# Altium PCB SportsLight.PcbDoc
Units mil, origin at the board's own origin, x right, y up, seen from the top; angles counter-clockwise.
Board outline 1968.64 x 1181.1 mil, 4 copper layers (Top Layer, GND02, PWR03, Bottom Layer), stack 23.756 mil thick; 45 components, 29 nets, 173 pads, 54 vias.
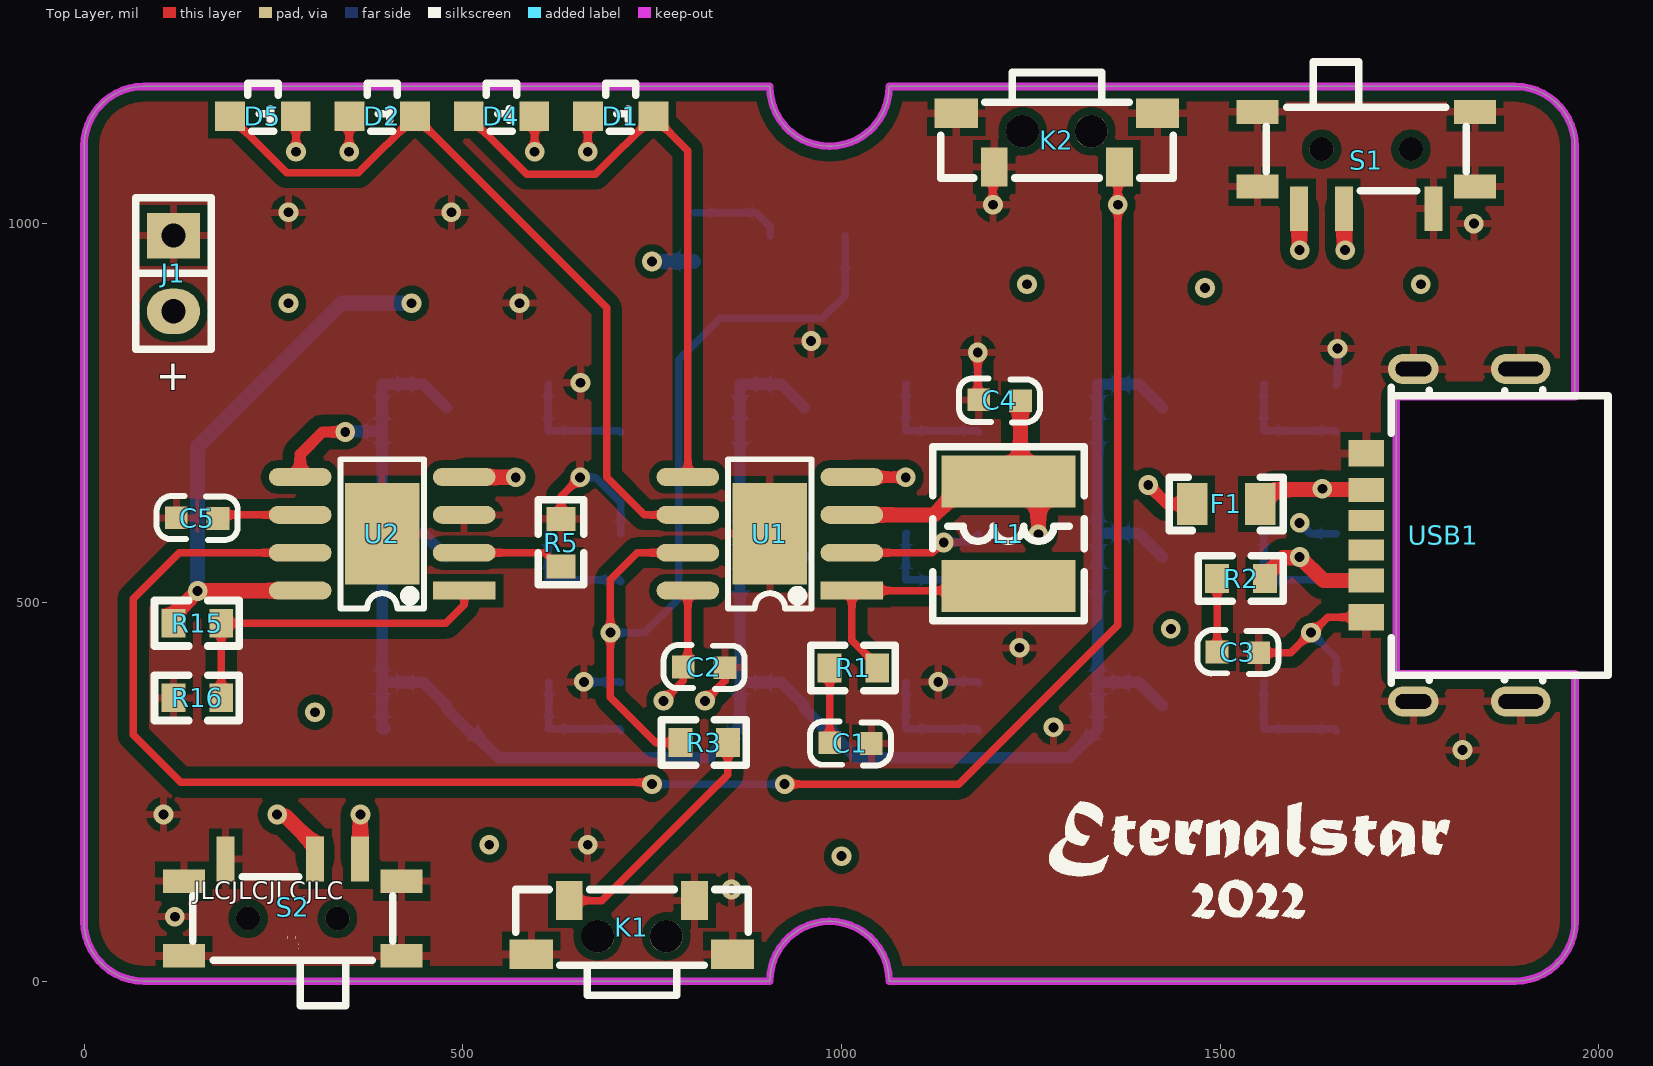
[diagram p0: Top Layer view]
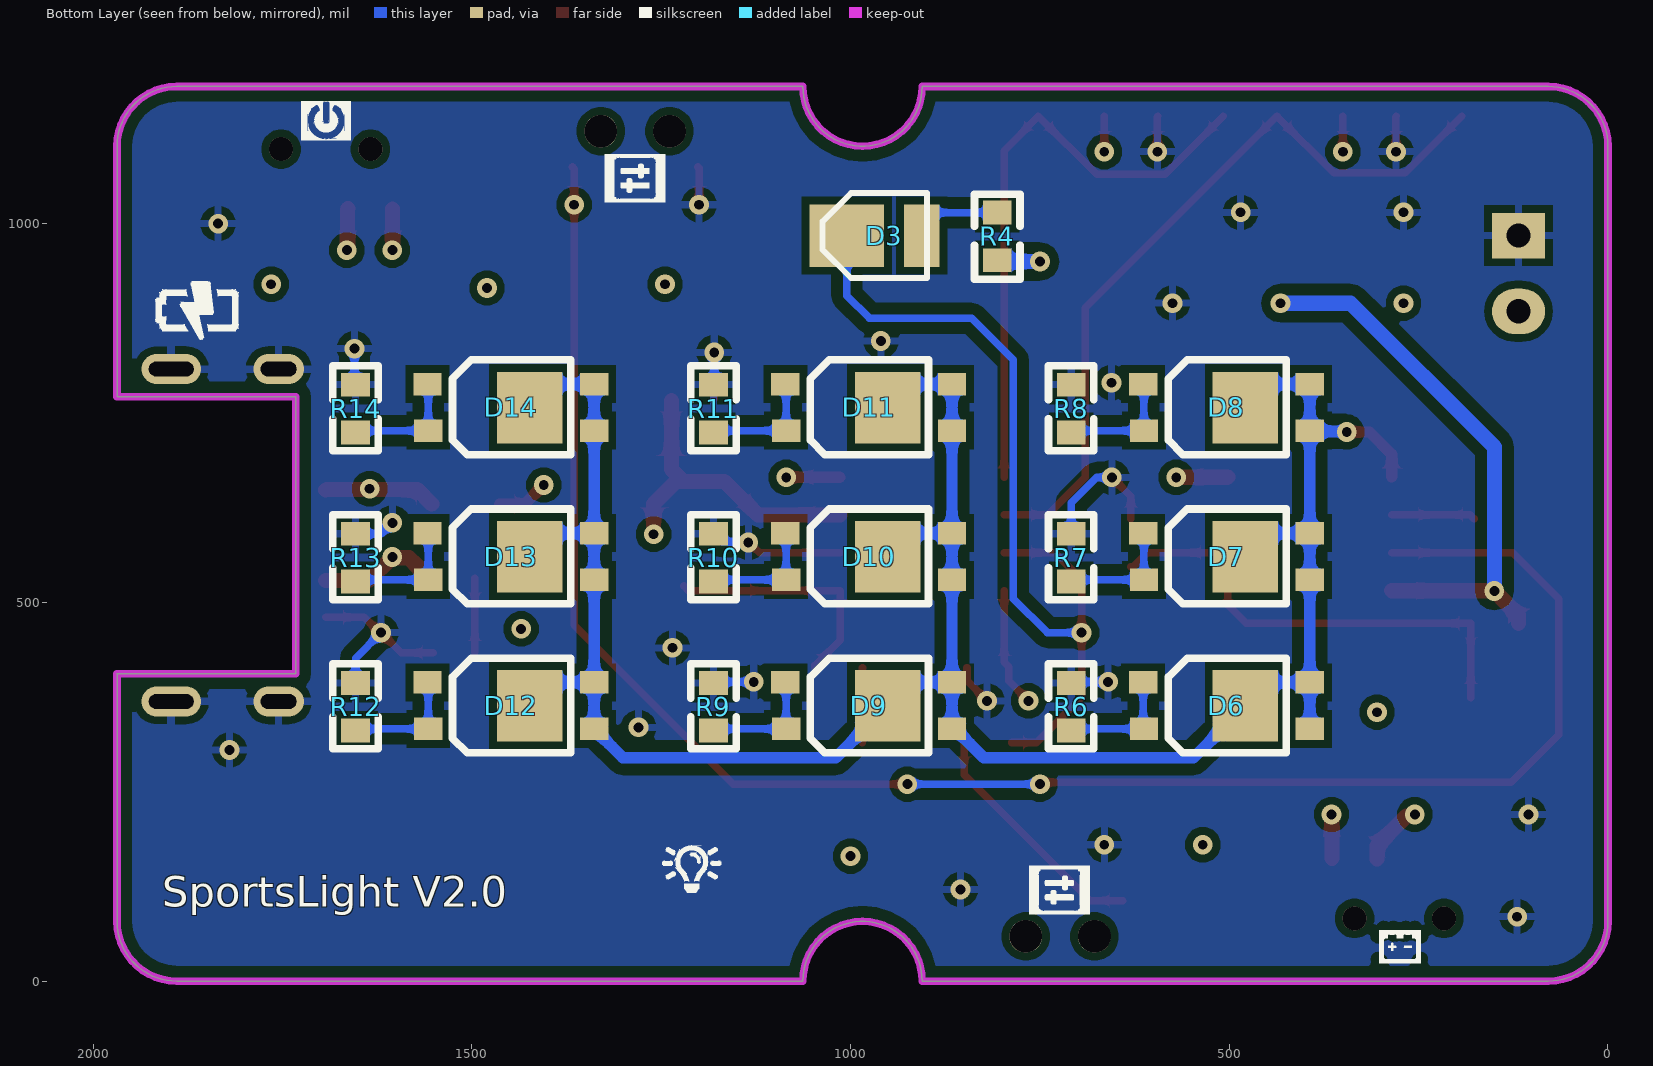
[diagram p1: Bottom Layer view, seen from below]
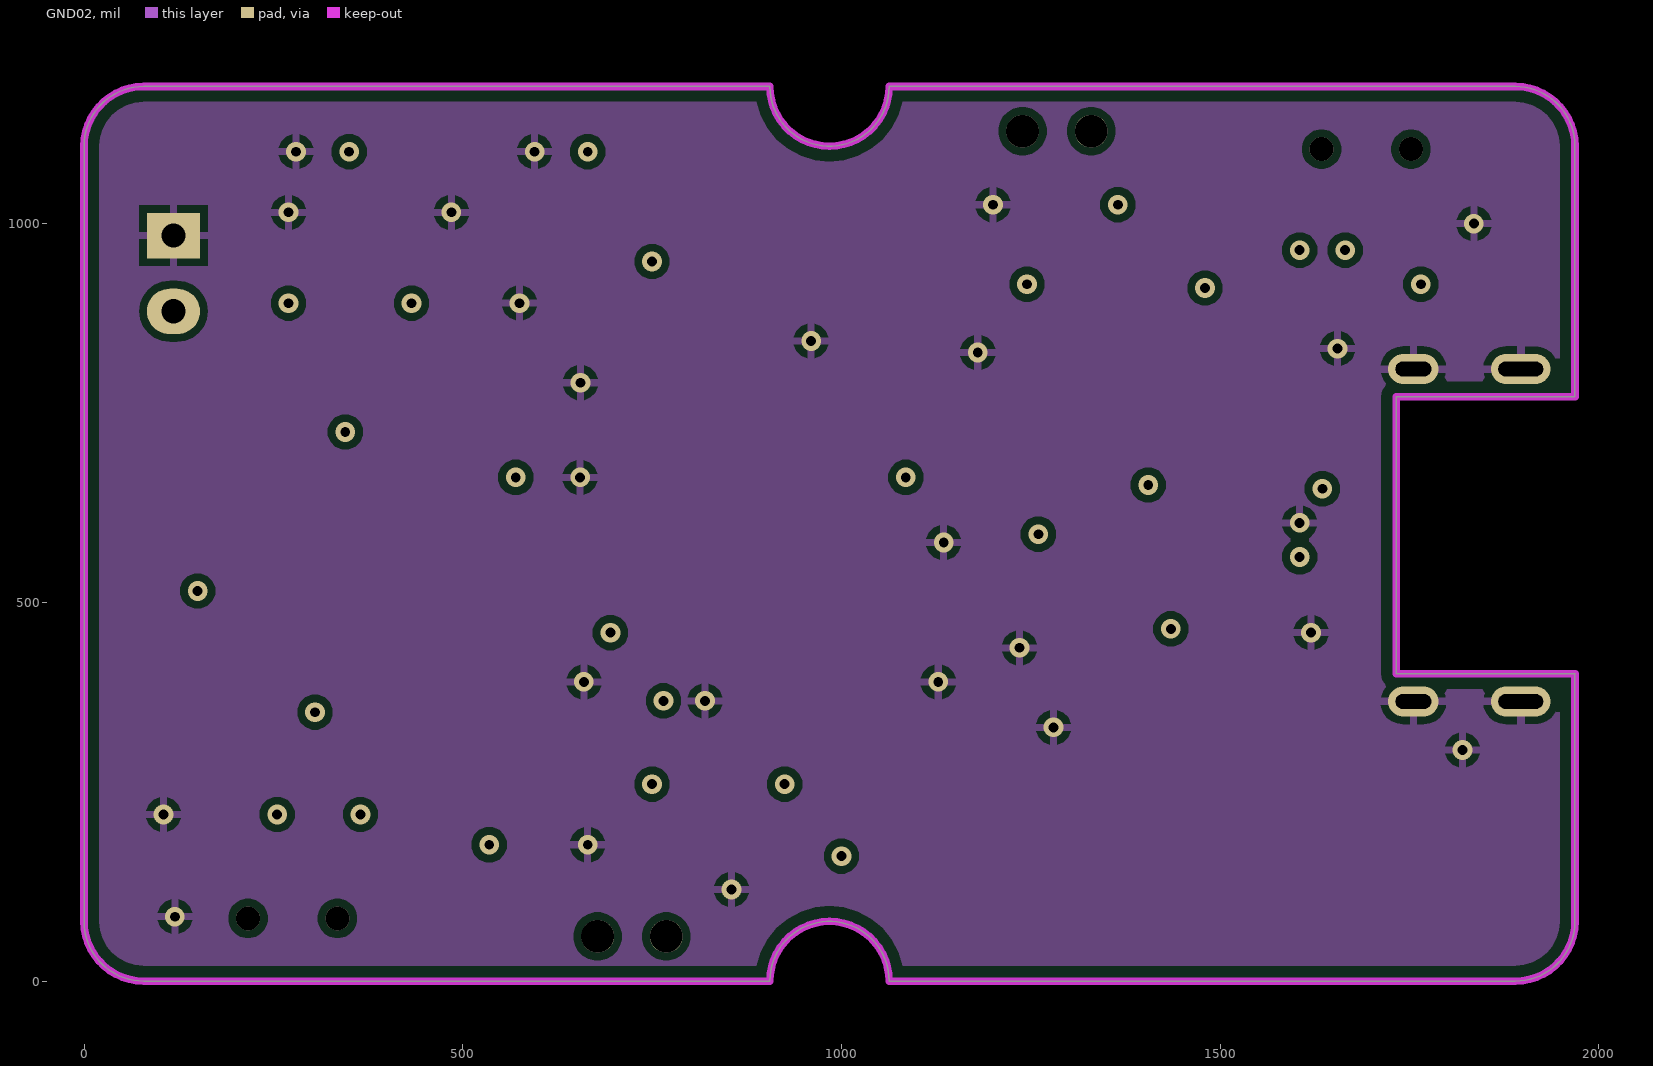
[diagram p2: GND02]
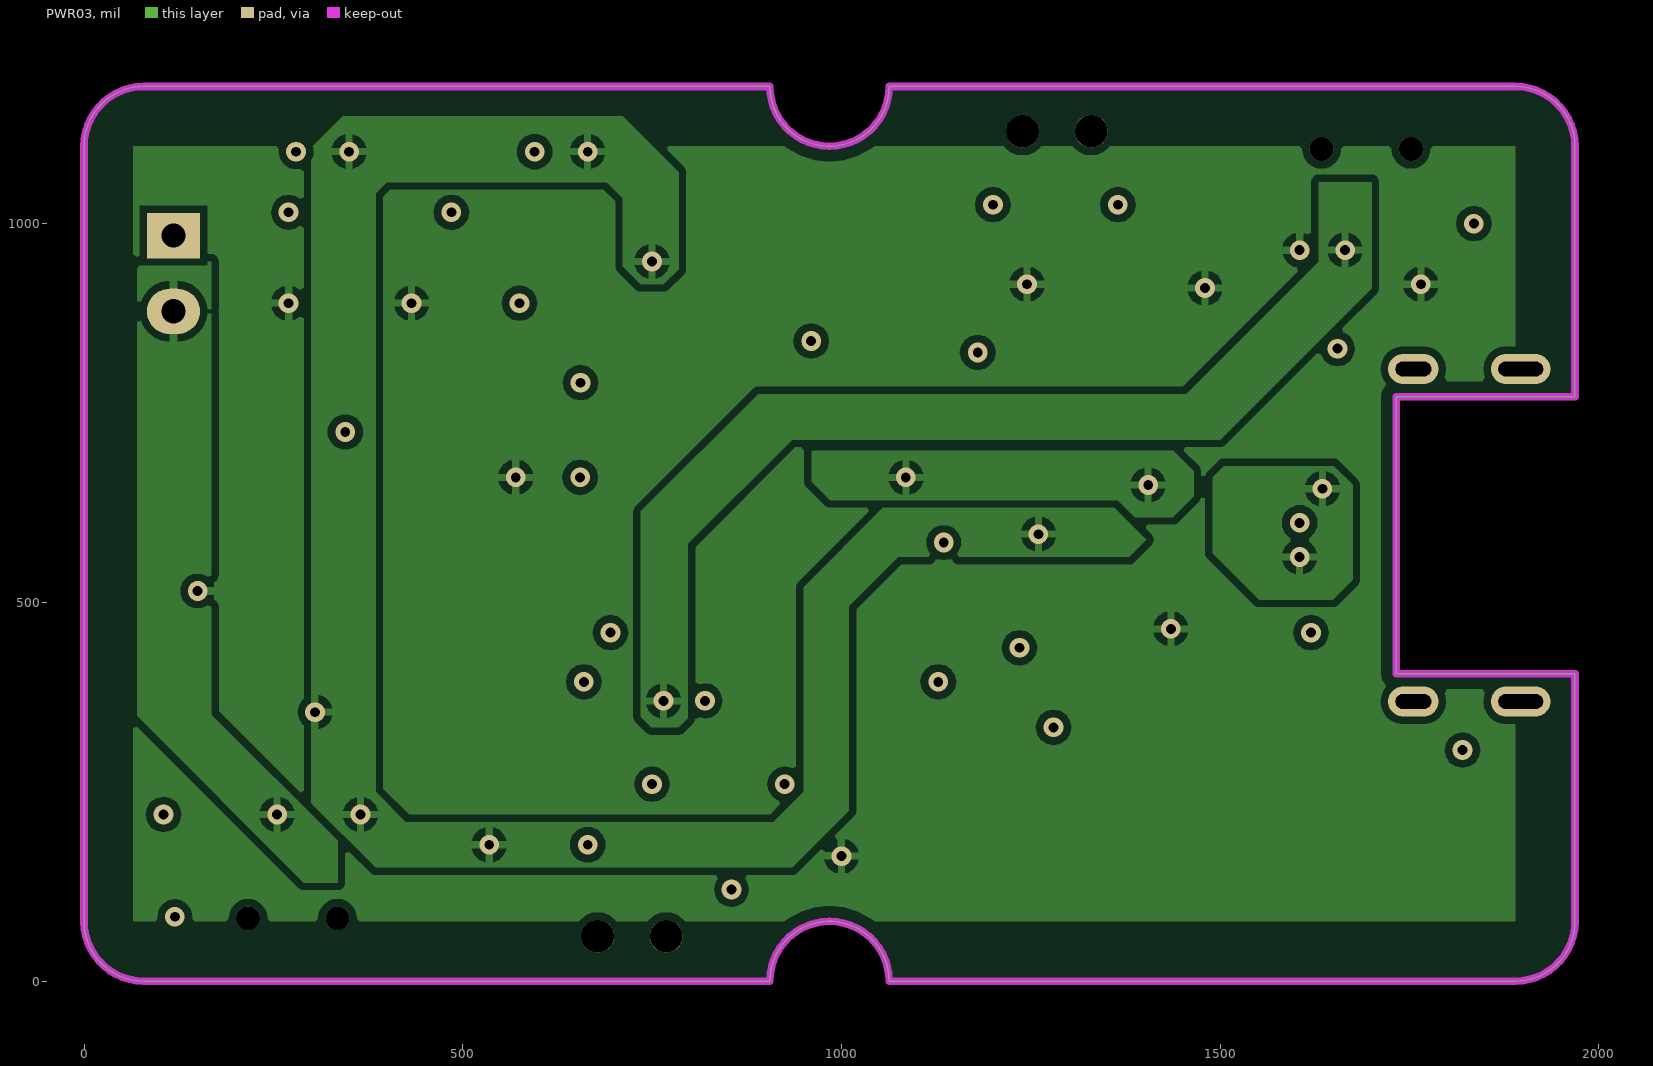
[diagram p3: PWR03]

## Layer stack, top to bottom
Top Solder: solder mask 0.4, Solder Resist, Dk 3.5
Top Layer: signal copper 1.4
Dielectric 1: dielectric 12.6, FR-4, Dk 4.8
GND02: signal copper 1.378
Dielectric 2: prepreg 2.8, PP-006, Dk 4.1
PWR03: signal copper 1.378
Dielectric 3: prepreg 2.8, PP-006, Dk 4.1
Bottom Layer: signal copper 1.4
Bottom Solder: solder mask 0.4, Solder Resist, Dk 3.5

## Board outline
78.74,0 905.51,0 cw(c984.25,0) 1062.99,0 1889.76,0 ccw(c1889.76,78.74) 1968.5,78.74 1968.5,405.38 1968.64,405.51 1732.28,405.51 1732.28,771.65 1968.5,771.65 1968.5,1102.49 1968.5,1102.36 ccw(c1889.76,1102.36) 1889.76,1181.1 1062.99,1181.1 cw(c984.25,1181.1) 905.51,1181.1 78.74,1181.1 ccw(c78.74,1102.36) 0,1102.36 0,78.74 ccw(c78.74,78.74)
cut-out: -1025,-915 -1015,-915 -1015,-905 -1025,-905
cut-out: -1025,-915 -1015,-915 -1015,-905 -1025,-905
cut-out: -1025,-915 -1015,-915 -1015,-905 -1025,-905

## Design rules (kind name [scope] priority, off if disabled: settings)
Clearance [All] p1: gap=10 ignorepadtopadclearanceinfootprint=TRUE except(15: Arc-Fill Arc-Poly Arc-Region Track-Fill Track-Poly Track-Region)
DiffPairsRouting [All] p1: maxlimit=10 minlimit=3.5 mostfreqgap=10 toplayer_minwidth=3.5 toplayer_maxwidth=15 toplayer_prefwidth=15 midlayer1_minwidth=3.5 midlayer1_maxwidth=15 midlayer1_prefwidth=15 midlayer2_minwidth=3.5 midlayer2_maxwidth=15 midlayer2_prefwidth=15 bottomlayer_minwidth=3.5 bottomlayer_maxwidth=15 bottomlayer_prefwidth=15 maxuncoupledlength=500
HoleSize [All] p1: absolutevalues=TRUE maxlimit=248.03 minlimit=7.87 maxpercent=80.000 minpercent=20.000
MinimumSolderMaskSliver [All] p1: minsoldermaskwidth=0
NetAntennae [InNet('No Net')] p1: netantennaetolerance=0
PolygonConnect [All] p1: connectstyle=Relief reliefconductorwidth=10 reliefentries=4 polygonreliefangle="90 Angle" airgapwidth=10
RoutingVias [All] p1: holewidth=28 width=50 viastyle="Through Hole" minholewidth=7.87 minwidth=15.75 maxholewidth=248.03 maxwidth=255.91
SilkToSolderMaskClearance [IsPad] p1: minsilkscreentomaskgap=0 clearancetoexposedcopper=TRUE
SolderMaskExpansion [All] p1: expansion=4 istentingtop=FALSE
Width [All] p1: maxlimit=30 minlimit=5 preferedwidth=10
25 further rules are at their usual default settings.

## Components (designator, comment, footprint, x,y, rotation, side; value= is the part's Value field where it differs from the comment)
C1 "3.3nF" 0603C 984.25,314.96 r0 top locked
C2 "10uF" 0603C 846.46,413.39 r180 top locked
C3 "1uF" 0603C 1551.13,433.07 r180 top locked
C4 "10uF" 0603C 1181.1,767.72 r0 top
C5 "MODE" 0603C 177.17,610.24 r180 top locked
D1 "LED4" LED-0602-RD 708.66,1141.73 r0 top locked
D2 "LED2" LED-0602-RD 393.7,1141.73 r0 top locked
D3 "LED-3528" LED-3528R 905.51,984.25 r0 bottom
D4 "LED3" LED-0602-RD 551.18,1141.73 r0 top locked
D5 "LED1" LED-0602-RD 236.22,1141.73 r0 top locked
D6 "LED-5630" LED-5630W 393.7,393.7 r180 bottom locked
D7 "LED-5630" LED-5630W 393.7,590.55 r180 bottom locked
D8 "LED-5630" LED-5630W 393.7,787.4 r180 bottom locked
D9 "LED-5630" LED-5630W 866.14,393.7 r180 bottom locked
D10 "LED-5630" LED-5630W 866.14,590.55 r180 bottom locked
D11 "LED-5630" LED-5630W 866.14,787.4 r180 bottom locked
D12 "LED-5630" LED-5630W 1338.58,393.7 r180 bottom locked
D13 "LED-5630" LED-5630W 1338.58,590.55 r180 bottom locked
D14 "LED-5630" LED-5630W 1338.58,787.4 r180 bottom
F1 "6V1A" FUSE-0805 1548.06,629.92 r180 top locked
J1 "CE" "Pin HDR1X2/2.54mm-S" 118.11,984.25 r0 top
K1 "KEY" SMD-3.5x7.8x2.5_C 590.55,35.43 r0 top locked
K2 "KEY" SMD-3.5x7.8x2.5_C 1417.32,1145.67 r180 top
L1 "1.5uH" CD43 1220.47,590.55 r270 top
R1 "0.5R" 0603R 984.25,413.39 r0 top locked
R2 "1K" 0603R 1496.06,531.5 r0 top locked
R3 "30K" 0603R 787.4,314.96 r0 top
R4 "33R" 0603R 806.36,951.63 r90 bottom locked
R5 "MODE" 0603R 629.92,610.24 r270 top locked
R6 "MODE" 0603R 708.66,393.7 r270 bottom locked
R7 "MODE" 0603R 708.66,590.55 r270 bottom
R8 "MODE" 0603R 708.66,787.4 r270 bottom locked
R9 "MODE" 0603R 1181.1,393.7 r270 bottom locked
R10 "MODE" 0603R 1181.1,590.55 r270 bottom locked
R11 "MODE" 0603R 1181.1,787.4 r270 bottom locked
R12 "MODE" 0603R 1653.54,393.7 r270 bottom locked
R13 "MODE" 0603R 1653.54,590.55 r270 bottom locked
R14 "MODE" 0603R 1653.54,787.4 r270 bottom locked
R15 "MODE" 0603R 118.11,472.44 r0 top locked
R16 "MODE" 0603R 118.11,374.02 r0 top locked
S1 "MSK-12C01-07" MSK-12C01-07 1692.91,1098.43 r180 top locked
S2 "MSK-12C01-07" MSK-12C01-07 275.59,82.68 r0 top locked
U1 "SY3511" ESOP8 905.51,590.55 r180 top locked
U2 "CN5730" ESOP8 393.7,590.55 r180 top
USB1 "USB-C 6P CB0.8(073)" USB-C-SMD_TYPE-C-6P-CB0.8-073 1692.91,480.32 r90 top locked

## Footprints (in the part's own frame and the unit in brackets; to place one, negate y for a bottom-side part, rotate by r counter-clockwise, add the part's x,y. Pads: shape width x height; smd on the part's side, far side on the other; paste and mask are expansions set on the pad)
0603C [mil]
  rect 30x30 smd: 1(0.21,-0.35) 2(55.21,-1.35)
  silkscreen extent -26,-30 81,28, body extent -1,-15 62,17, height 12
0603R [mm]
  rect 0.8x0.965 smd: 1(0,0) 2(1.6,0)
  silkscreen extent -0.64,-0.76 2.21,0.76, body extent -0.04,-0.41 1.56,0.41, height 0.45
CD43 [mm] "4.5*4*3.2mm（长宽高）"
  rect 1.75x4.5 smd: 1(-1.75,0) 2(1.75,0)
  silkscreen extent -2.92,-2.54 2.92,2.54, body extent -2.13,-1.87 2.29,2.13, height 3.3
ESOP8 [mm]
  rect 2.1x0.6 smd: 1(-2.75,1.905)
  oval 2.1x0.6 smd: 2(-2.75,0.635) 3(-2.75,-0.635) 4(-2.75,-1.905) 5(2.75,-1.905) 6(2.75,-0.635) 7(2.75,0.635) 8(2.75,1.905)
  rect 2.5x3.4 smd paste-2: 9(0,0)
  rect 0.9x0.7 on Top Paste: 10(-0.625,1.1) 10(-0.625,0) 10(-0.625,-1.1) 11(0.65,1.1) 11(0.65,0) 11(0.65,-1.1)
  silkscreen extent -1.4,-2.5 1.4,2.5, body extent -3.05,-2.5 2.95,2.5, height 1.53
FUSE-0805 [mil]
  rect 40x55 smd: 1(-5,0) 2(85,0)
  silkscreen extent -35,-35 115,35, body extent 0,-24 79,24, height 20
LED-0602-RD [mm]
  rect 1x1 smd: 1(-1.1,0) 2(1.1,0)
  silkscreen extent -0.51,-0.51 0.51,1.11
LED-3528R [mm]
  rect 1.2x2.1 smd: A(0.013,0)
  rect 2.5x2.1 smd: K(2.527,0)
  silkscreen extent -0.17,-1.42 3.34,1.42, body extent -0.25,-1.4 3.25,1.4, height 1.95
LED-5630W [mm]
  rect 2.2x2.4 smd: A(-2.159,-0.768)
  rect 0.95x0.75 smd: A(0,-1.543) A(0,0.019) K(-5.588,0.019) K(-5.563,-1.543)
  silkscreen extent -4.75,-2.34 -0.79,0.83, body extent -5.57,-2.29 0.23,0.71, height 0.95
MSK-12C01-07 [mm]
  rect 1.4x0.8 smd: 0(-3.65,-1.25) 0(-3.65,1.25) 0(3.65,-1.25) 0(3.65,1.25)
  rect 0.6x1.5 smd: 1(2.25,1.996) 2(0.75,1.996) 3(-2.25,1.996)
  round 0.8 hole 0.8: " "(-1.5,0) " "(1.5,0)
  silkscreen extent -3.35,-2.92 3.35,1.4, body extent -3.92,-2.89 3.92,2.41, height 1.5
"Pin HDR1X2/2.54mm-S" [mil]
  rect 70x60 hole 32: 1(0,0)
  oval 70x60 hole 32: 2(0,-100)
  silkscreen extent -50,-150 50,50, body extent -50,-150 50,50, height 336
SMD-3.5x7.8x2.5_C [mm]
  rect 1.45x1 smd: 1(0,0) 2(6.75,0)
  rect 0.9x1.3 smd: 3(1.275,1.8) 4(5.475,1.8)
  round 1.1 hole 1.1 unplated: ""(2.225,0.6) ""(4.525,0.6)
  silkscreen extent -0.52,-1.37 7.27,2.17
USB-C-SMD_TYPE-C-6P-CB0.8-073 [mm]
  rect 0.9x1.2 smd: 1(0,0) 6(5.5,0)
  rect 0.8x1.2 smd: 2(1.23,0) 5(4.27,0)
  rect 0.7x1.2 smd: 3(2.25,0) 4(3.25,0)
  oval 1x1.7 hole 0.5 slot 1.2 at 90 deg: 7(-2.825,-1.58) 8(8.325,-1.58)
  oval 1x2 hole 0.5 slot 1.5 at 90 deg: 7(-2.825,-5.18) 8(8.325,-5.18)
  silkscreen extent -2.21,-8.11 7.71,-0.84

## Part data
C1 C2 C3 C4 C5: library part CAP, "无极性电容"
D1 D2 D4 D5: library part LED
F1: library part FUSE
J1: library part "Pin HDR1X2"
L1: library part INDUCTOR, "INDUCTOR"
R1 R2 R3 R4 R5 R6 R7 R8 R9 R10 R11 R12 R13 R14 R15 R16: library part RES
U1: "移动电源单芯片"
U2: "LED集成驱动电路"

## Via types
v1: diameter 26, hole 13, Top Layer to Bottom Layer, 54 vias

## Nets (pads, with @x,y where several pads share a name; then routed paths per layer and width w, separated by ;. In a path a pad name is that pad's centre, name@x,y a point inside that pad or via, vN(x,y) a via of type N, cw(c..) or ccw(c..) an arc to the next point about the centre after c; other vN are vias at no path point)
BAT: C4.2 D1.1 D2.1 L1.1 R4.1 S2.1 U1.3 | length 640
  Top Layer w10: v1(350,1095) 350,1141.34 D2.1 ; v1(665,1095) 665,1141.38 D1.1
  Top Layer w15: S2.1 S2.1@364.59,161.67 ; v1@364.59,219.59 v1(365,220)
  Top Layer w20: S2.1@364.59,161.67 v1@364.59,219.59 ; U1.3 1122.44,615.55 1166.34,659.45 L1.1 ; C4.2 1236.32,675.29 L1.1 ; v1(1260,590) 1260,630 1230.55,659.45 L1.1
  Bottom Layer w10: R4.1@804.73,950 R4.1
  Bottom Layer w20: v1(750,950) R4.1@804.73,950
  other v1: 535,180 305,355
GND: C1.2 C2.1 C3.1 C4.1 C5.2 D4.2 D5.2 J1.1 K1.1 K1.2 K1.4 K2.1 K2.2 K2.4 R5.1 R6.1 R7.1 R8.1 R9.1 R10.1 R11.1 R12.1 R13.1 R14.1 R16.1 S1.0 S1.3 S2.0 S2.3 U1.2 U1.9 U2.3 U2.9 USB1.1 USB1.6 USB1.7 USB1.8 | length 1103.8
  Top Layer w10: D5.2 280,1141.26 v1(280,1095) ; D4.2 595,1141.22 v1(595,1095) ; R5.1 629.92,639.92 v1(655,665) ; v1(820,370) 846.24,396.24 C2.1 ; U1.2 1120.13,565.55 1125.68,571.1 1127,571.1 v1(1135,579.1) ; v1(1180,830) 1180,768.68 C4.1 ; v1(1200,1025) 1200,1073.03 K2.4 ; C3.1 1593.43,433.43 v1(1620,460) 1621.8,460 1642.11,480.32 USB1.1
  Bottom Layer w10: v1(655,665) 675,665 708.66,631.34 R7.1 ; v1(660,395) 707.36,395 R6.1 ; v1(1127.84,395) 1179.8,395 R9.1 ; v1(1135,579.1) 1135.7,579.8 1170.35,579.8 R10.1 ; v1(1180,830) 1180,788.5 R11.1 ; v1(1605,605) 1605.1,605 1619.55,590.55 R13.1 ; v1(1620,460) 1653.54,426.46 R12.1 ; R14.1 1655,788.86 v1(1655,835)
  other v1: 120,85 854.94,120.87 665,180 105,220 1820,305 1280,335 1235,440 655.4,790 960,845 575,895 1835,1000 270,1015 485,1015
MODE: R15.2 R16.2 U2.1 | length 448
  Top Layer w10: R16.2 R15.2 477.44,472.44 501.97,496.97 U2.1
NetC1_1: C1.1 R1.1 | length 98.9
  Top Layer w10: R1.1 984.46,413.17 C1.1
NetC2_2: C2.2 S1.2 U1.8 | length 214.4
  Top Layer w10: v1(765,370) 791.24,396.24 C2.2 797.24,420.74 U1.8
  Top Layer w20: S1.2 1664.19,1019.04 1664.19,965.81 v1(1665,965)
NetC3_2: C3.2 R2.1 | length 97.1
  Top Layer w10: C3.2 1496.06,434.57 R2.1
NetC5_1: C5.1 U2.6 | length 110.5
  Top Layer w10: C5.1 181.91,615.55 U2.6
NetD1_K: D1.2 D4.1 U1.5 | length 802.6
  Top Layer w10: D4.1 584.61,1065 675.24,1065 D1.2 797.24,1096.46 U1.5
NetD2_K: D2.2 D5.1 U1.6 | length 1015.3
  Top Layer w10: D5.1 267.65,1067 362.28,1067 D2.2 690,888.74 690,665 739.45,615.55 U1.6
NetD3_A: D3.A R4.2 | length 119.1
  Bottom Layer w10: R4.2 887.39,1014.62 906.01,996 D3.A
NetD3_K: D3.K R3.1 U1.7 | length 1147.3
  Top Layer w10: R3.1 755.04,314.96 695,375 v1(695,460) 695,530 730.55,565.55 U1.7
  Bottom Layer w10: v1(695,460) 740,460 785,505 785,820 840,875 975,875 1005.01,905.01 D3.K
NetD6_A: D6.A D7.A D8.A D9.A D10.A D11.A D12.A D13.A D14.A U2.5 | length 3272.8
  Top Layer w15: U2.5 285.43,695.43 315,725 v1(345,725)
  Bottom Layer w15: v1(345,725) 345.83,725.83 392.88,725.83 D8.A@393.7,726.65 ; D6.A@397.64,332.95 393.7,332.95 D6.A@393.7,394.45 ; D7.A@478.7,560.3 447.7,591.3 D7.A@393.7,591.3 ; D8.A@478.7,757.15 447.7,788.15 393.7,788.15 D8.A@393.7,726.65 ; D9.A@870.08,332.95 D9.A@866.14,332.95 ; D10.A@951.14,560.3 920.14,591.3 D10.A@866.14,591.3 ; D11.A@951.14,757.15 920.14,788.15 866.14,788.15 866.14,726.65 D10.A@866.14,591.3 ; D12.A@1423.58,363.45 1392.58,394.45 D12.A@1338.58,394.45 ; D13.A@1423.58,560.3 1392.58,591.3 D13.A@1338.58,591.3 ; D14.A@1423.58,757.15 1392.58,788.15 1338.58,788.15 1338.58,726.65 D13.A@1338.58,591.3 ; D6.A@393.7,394.45 447.7,394.45 478.7,363.45 478.7,359.51 514.51,323.71 518.44,323.71 547.19,294.96 824.21,294.96 862.2,332.95 D9.A@866.14,332.95 ; D6.A@393.7,394.45 393.7,529.8 D7.A@393.7,591.3 ; D7.A@393.7,591.3 D8.A@393.7,726.65 ; D9.A@866.14,332.95 D9.A@866.14,394.45 ; D9.A@866.14,394.45 920.14,394.45 951.14,363.45 951.14,359.51 986.95,323.71 990.89,323.71 1019.63,294.96 1300.59,294.96 1338.58,332.95 D12.A@1338.58,394.45 ; D9.A@866.14,394.45 866.14,529.8 D10.A@866.14,591.3 ; D12.A@1338.58,394.45 1338.58,529.8 D13.A@1338.58,591.3
NetD6_K: D6.K R6.2 | length 158.8
  Bottom Layer w10: D6.K@613.7,394.45 613.7,333.95 612.7,332.95 706.42,332.95 R6.2
NetD7_K: D7.K R7.2 | length 158.8
  Bottom Layer w10: D7.K@613.7,591.3 612.7,590.3 612.7,529.8 706.42,529.8 R7.2
NetD8_K: D8.K R8.2 | length 158.8
  Bottom Layer w10: D8.K@613.7,788.15 612.7,787.15 612.7,726.65 706.42,726.65 R8.2
NetD9_K: D9.K R9.2 | length 158.8
  Bottom Layer w10: D9.K@1086.14,394.45 1085.14,393.45 1085.14,332.95 1178.86,332.95 R9.2
NetD10_K: D10.K R10.2 | length 158.8
  Bottom Layer w10: D10.K@1086.14,591.3 1085.14,590.3 1085.14,529.8 1178.86,529.8 R10.2
NetD11_K: D11.K R11.2 | length 158.8
  Bottom Layer w10: D11.K@1086.14,788.15 1085.14,787.15 1085.14,726.65 1178.86,726.65 R11.2
NetD12_K: D12.K R12.2 | length 158.8
  Bottom Layer w10: D12.K@1558.58,394.45 1557.58,393.45 1557.58,332.95 1651.3,332.95 R12.2
NetD13_K: D13.K R13.2 | length 158.8
  Bottom Layer w10: D13.K@1558.58,591.3 1557.58,590.3 1557.58,529.8 1651.3,529.8 R13.2
NetD14_K: D14.K R14.2 | length 158.8
  Bottom Layer w10: D14.K@1558.58,788.15 1557.58,787.15 1557.58,726.65 1651.3,726.65 R14.2
NetF1_2: F1.2 U1.4 | length 139.9
  Top Layer w10: U1.4 U1.4@1014.06,665.28 ; v1@1084.72,665.28 v1(1085,665)
  Top Layer w15: U1.4@1014.06,665.28 v1@1084.72,665.28 ; v1(1405,655) 1430.08,629.92 F1.2
NetJ1_2: J1.2 S2.2 | length 84.8
  Top Layer w20: v1(255,220) 257.1,217.9 266.2,217.9 305.12,178.98 S2.2
NetK1_1: K1.3 R3.2 | length 320.7
  Top Layer w10: K1.3 683.8,106.3 850,272.5 850,314.57 R3.2
NetK2_1: K2.3 U2.7 | length 2445.1
  Top Layer w10: U2.7 125.55,565.55 65,505 65,325 127.5,262.5 747.5,262.5 v1(750,260) ; v1(925,260) 1155,260 1365,470 v1(1365,1025) 1365,1072.68 K2.3
  Bottom Layer w10: v1(750,260) v1(925,260)
NetL1_2: L1.2 R1.2 U1.1 | length 325.2
  Top Layer w10: R1.2 1047.24,416.63 1013.78,450.1 U1.1 1214.37,515.55 L1.2
NetR5_2: R5.2 U2.2 | length 135.5
  Top Layer w10: U2.2 608.37,565.55 626.67,547.24 R5.2
VBUS: F1.1 R2.2 USB1.2 USB1.5 | length 309.3
  Top Layer w20: F1.1 1571.99,648.85 1633.85,648.85 v1(1635,650) 1635.79,649.21 1692.13,649.21 USB1.5 ; R2.2 1559.05,534.74 1583.16,558.85 1603.85,558.85 v1(1605,560) 1636.26,528.74 USB1.2
VCC_5V: R15.1 S1.1 U2.4 U2.8 | length 866
  Top Layer w10: S1.1 S1.1@1604.67,1019.51 ; v1@1604.67,965.33 v1(1605,965)
  Top Layer w20: R15.1 118.11,483.11 v1(150,515) 150.28,515.28 285.16,515.28 U2.8 ; U2.4 502.24,665.28 569.72,665.28 v1(570,665) ; v1@1604.67,965.33 S1.1@1604.67,1019.51
  Bottom Layer w20: v1(150,515) 150,705 340,895 v1(432.46,895)
  other v1: 1000,165 1435,465 270,895 1480,915 1245,920 1765,920
pads on no net: "S1. " "S2. " K1. K2. U1.10 U1.11 U2.10 U2.11 USB1.3 USB1.4

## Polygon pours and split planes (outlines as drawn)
VCC_5V on PWR03 "VCC_5V_L03_P013" (solid, pour order 13): 65,78.74 984.25,78.74 1889.76,78.74 1889.76,326.64 1889.76,405.51 1732.28,405.51 1732.28,771.65 1889.76,771.65 1889.76,1102.36 984.29,1102.36 cw(c984.26,1181.31) 979.81,1102.49 65,1102.36
NetJ1_2 on PWR03 "NETJ1_2_L03_P010" (solid, pour order 10): 335,130 335,185 168.11,351.89 168.11,950 70,950 70,932.36 70,350 290,130
BAT on PWR03 "BAT_L03_P008" (solid, pour order 8): 385,1040 400,1055 690,1055 711.5,1033.5 711.5,943.5 735,920 765,920 785,940 785,1068.1 711.5,1141.73 341.73,1141.73 300,1100 300,235 385,150 935,150 1010,225 1010,495 1075,560 1380,560 1402.5,582.5 1360,625 1055,625 950,520 950,250 910,210 425,210 385,250
NetC2_2 on PWR03 "NETC2_2_L03_P003" (solid, pour order 3): 785,335 797.29,347.29 797.24,347.29 797.24,577.24 935,715 1500,715 1700,915 1700,1055 1630,1055 1630,950 1455,775 890,775 735,620 735,348.7 748.7,335
NetF1_2 on PWR03 "NETF1_2_L03_P002" (solid, pour order 2): 1387.5,612.5 1437.5,612.5 1465,640 1465,672.96 1437.96,700 960.51,700 960.51,659.49 985,635 1365,635
VBUS on PWR03 "VBUS_L03_P001" (solid, pour order 1): 1648.55,503.55 1675,530 1675,655 1650,680 1505,680 1490,665 1490,565 1551.45,503.55
GND on GND02 "GND_L02_P014" (solid, pour order 14): 78.74,0 905.51,0 cw(c984.25,0) 1062.99,0 1889.76,0 ccw(c1889.76,78.74) 1968.5,78.74 1968.5,405.38 1968.64,405.51 1732.28,405.51 1732.28,771.65 1968.5,771.65 1968.5,1102.49 1968.5,1102.36 ccw(c1889.76,1102.36) 1889.76,1181.1 1062.99,1181.1 cw(c984.25,1181.1) 905.51,1181.1 78.74,1181.1 ccw(c78.74,1102.36) 0,1102.36 0,78.74 ccw(c78.74,78.74)
GND on Top Layer "GND_L01_P015" (solid, pour order 15): 78.74,0 905.51,0 cw(c984.25,0) 1062.99,0 1889.76,0 ccw(c1889.76,78.74) 1968.5,78.74 1968.5,405.38 1968.64,405.51 1732.28,405.51 1732.28,771.65 1968.5,771.65 1968.5,1102.49 1968.5,1102.36 ccw(c1889.76,1102.36) 1889.76,1181.1 1062.99,1181.1 cw(c984.25,1181.1) 905.51,1181.1 78.74,1181.1 ccw(c78.74,1102.36) 0,1102.36 0,78.74 ccw(c78.74,78.74)
GND on Bottom Layer "GND_L04_P016" (solid, pour order 16): 78.74,0 905.51,0 cw(c984.25,0) 1062.99,0 1889.76,0 ccw(c1889.76,78.74) 1968.5,78.74 1968.5,405.38 1968.64,405.51 1732.28,405.51 1732.28,771.65 1968.5,771.65 1968.5,1102.49 1968.5,1102.36 ccw(c1889.76,1102.36) 1889.76,1181.1 1062.99,1181.1 cw(c984.25,1181.1) 905.51,1181.1 78.74,1181.1 ccw(c78.74,1102.36) 0,1102.36 0,78.74 ccw(c78.74,78.74)

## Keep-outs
Keep-Out Layer:
  lines w10: 1968.5,405.38 1968.5,78.74 cw(c1889.76,78.74) 1889.76,0 1062.99,0 ccw(c984.25,0) 905.51,0 78.74,0 cw(c78.74,78.74) 0,78.74 0,1102.36 cw(c78.74,1102.36) 78.74,1181.1 905.51,1181.1 ccw(c984.25,1181.1) 1062.99,1181.1 1889.76,1181.1 cw(c1889.76,1102.36) 1968.5,1102.36 ; 1968.5,1102.49 1968.5,771.65 1732.28,771.65 1732.28,405.51 1968.64,405.51

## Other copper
Bottom Layer:
  region: 303.52,59.78 303.51,59.79 303.51,59.8 303.53,59.78 303.52,59.78
  region: 249.17,61.79 249.17,61.81 249.21,61.8 249.17,61.78
  region: 250.88,61.99 250.87,62.02 250.92,62.02 250.92,62 250.89,61.98 250.88,61.99
  region: 303.21,60.44 303.2,60.48 303.21,60.48 303.22,60.47 303.22,60.45
  region: 247.24,28.95 247.24,28.97 247.26,28.97 247.25,28.91 247.24,28.91 247.24,28.93
  region: 300.79,26.79 300.81,26.78 300.82,26.76 300.78,26.76 300.77,26.78 300.78,26.79
  region: 283.53,69.22 283.54,69.24 283.58,69.25 283.6,69.23 283.59,69.21 283.55,69.21 283.54,69.22
  region: 247.24,59.8 247.25,59.79 247.24,59.79
  region: 283.83,69.07 283.81,69.08 283.8,69.09 283.83,69.11 283.85,69.09 283.83,69.07
  region: 282.04,62.02 282.08,62.01 282.09,62.01 282.06,61.98 282.04,61.99 282.03,62.02
  region: 282.7,67.13 282.7,67.1 282.68,67.06 282.67,67.04 282.65,67.05 282.63,67.06 282.64,67.14 282.68,67.15 282.69,67.13
  region: 250,62 249.95,61.99 249.95,62 249.97,62.02 250,62.01
  region: 301.64,26.97 301.62,26.97 301.62,26.99 301.67,26.98 301.66,26.97 301.65,26.97
  region: 249.95,26.76 249.95,26.78 249.97,26.79 249.99,26.78 249.99,26.76 249.96,26.76
  region: 266.96,69.09 266.95,69.07 266.93,69.07 266.92,69.08 266.93,69.1 266.95,69.11 266.96,69.1
  region: 267.24,69.23 267.23,69.2 267.18,69.2 267.16,69.22 267.17,69.24 267.18,69.26 267.24,69.25 267.24,69.24
  region: 268.13,68.3 268.12,68.3 268.13,68.31 268.13,68.3
  region: 268.73,62 268.71,61.98 268.68,61.99 268.68,62.02 268.71,62.03 268.74,62.01 268.74,62
  region: 299.89,61.99 299.86,61.98 299.84,62 299.84,62.02 299.88,62.03 299.9,62.01 299.89,62
  region: 295.72,69.2 295.68,69.21 295.69,69.25 295.73,69.26 295.75,69.25 295.77,69.23 295.76,69.21 295.73,69.2
  region: 268.07,67.07 268.06,67.11 268.08,67.15 268.13,67.13 268.13,67.06 268.11,67.04 268.09,67.04 268.08,67.06 268.07,67.07
  region: 296.68,68.3 296.69,68.29 296.7,68.26 296.68,68.24 296.66,68.26 296.67,68.29
  region: 300.8,61.99 300.76,62 300.77,62.01 300.81,62.01 300.81,62
  region: 301.59,61.81 301.61,61.79 301.57,61.78 301.54,61.8 301.58,61.82
  region: 249.1,26.97 249.09,26.98 249.14,26.99 249.14,26.97 249.11,26.97
  region: 255.02,69.21 255,69.22 255.02,69.24 255.05,69.25 255.07,69.23 255.06,69.21 255.03,69.21
  region: 282.63,62.63 282.65,62.68 282.67,62.69 282.68,62.63 282.67,62.58 282.65,62.58 282.63,62.62
  region: 268.08,62.66 268.09,62.69 268.1,66.99 268.11,66.99 268.12,66.93 268.12,62.67 268.13,62.63 268.12,62.58 268.1,62.58 268.08,62.59 268.07,62.63 268.08,62.65
  region: 282.64,66.33 282.65,66.99 282.67,66.99 282.67,62.73 282.66,62.72 282.64,62.77 282.65,62.82 282.64,62.85 282.64,66.32
  region: 303.53,28.95 303.54,28.93 303.52,28.91 303.51,28.91 303.52,28.98 303.54,28.96

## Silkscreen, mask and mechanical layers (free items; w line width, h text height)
Top Overlay:
  drawing of 68 lines, arcs and shapes, not listed
  text "+" at 95,780 h40
  text "JLCJLCJLCJLC" at 145,100 h40
Bottom Overlay:
  drawing of 146 lines, arcs and shapes, not listed
  text "SportsLight V2.0" at 1908.56,98.43 h40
